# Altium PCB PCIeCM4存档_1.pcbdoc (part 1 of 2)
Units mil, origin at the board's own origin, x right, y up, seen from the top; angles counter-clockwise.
Board outline 9275 x 6345 mil, 4 copper layers (Top Layer, GND, 3V3, Bottom Layer); 98 components, 111 nets, 637 pads, 303 vias.
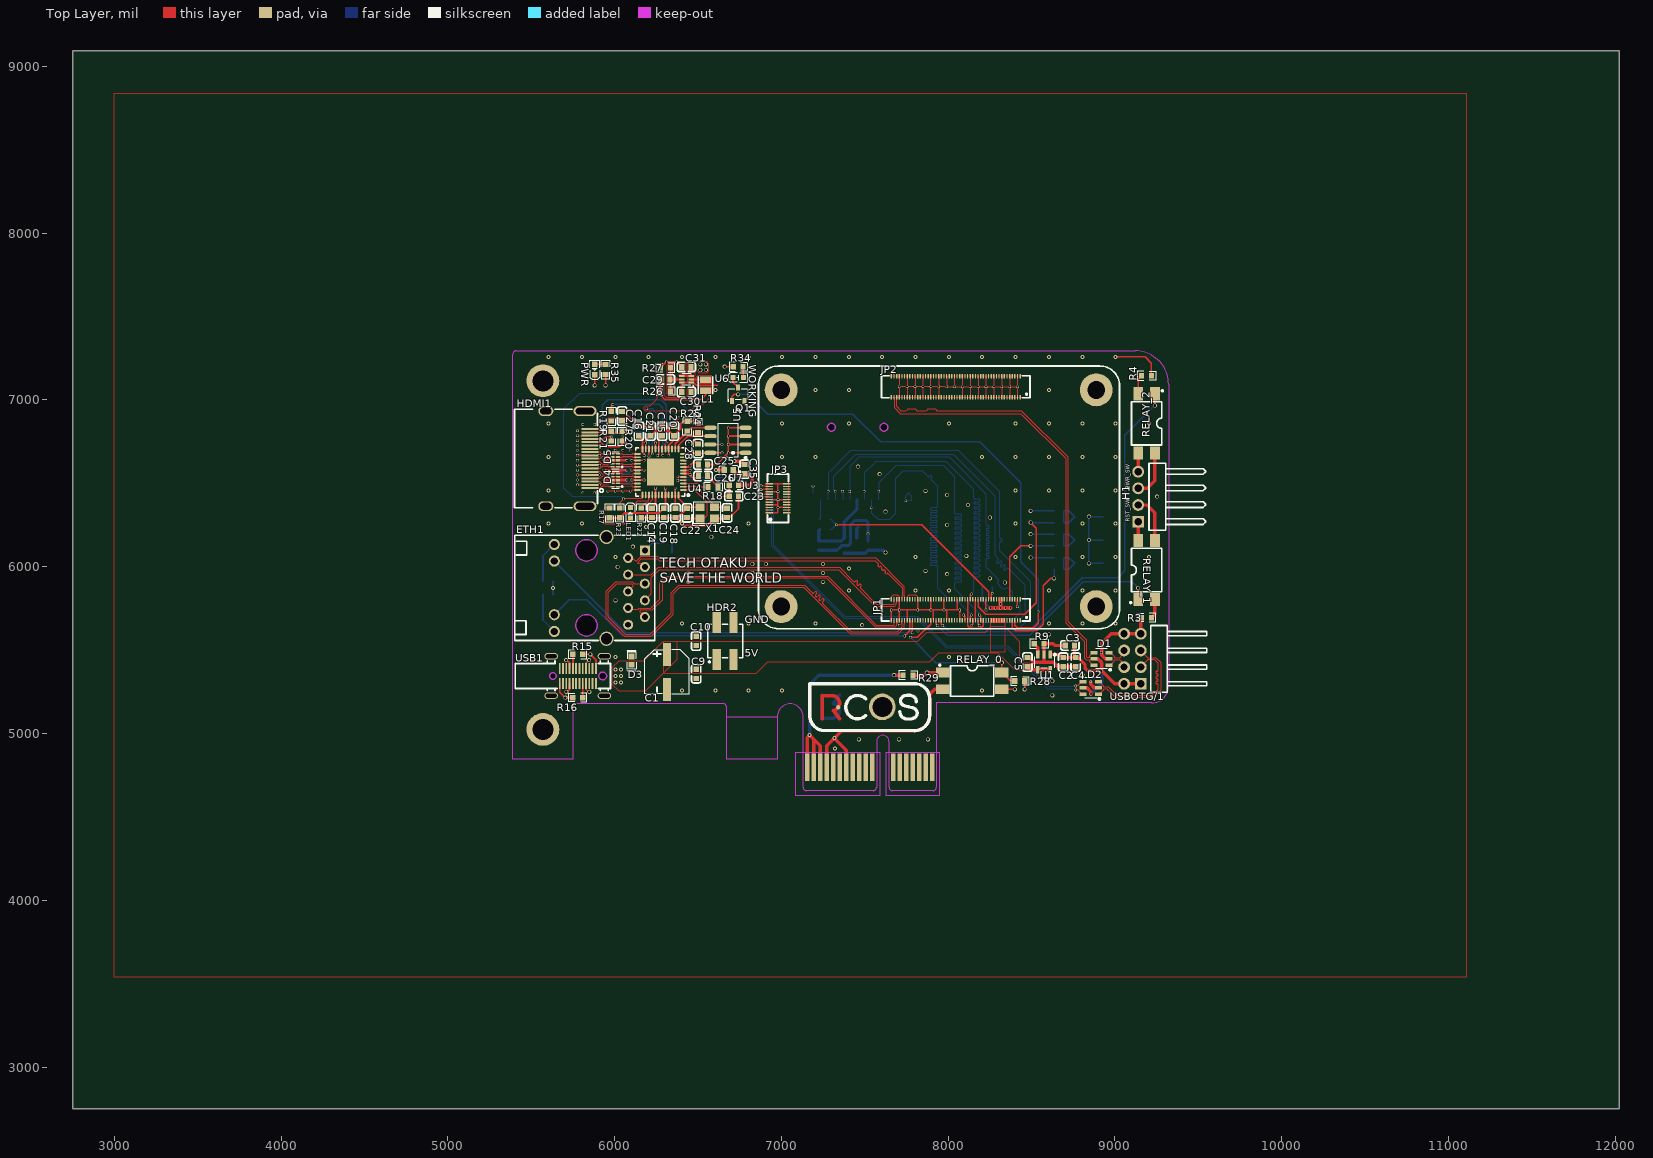
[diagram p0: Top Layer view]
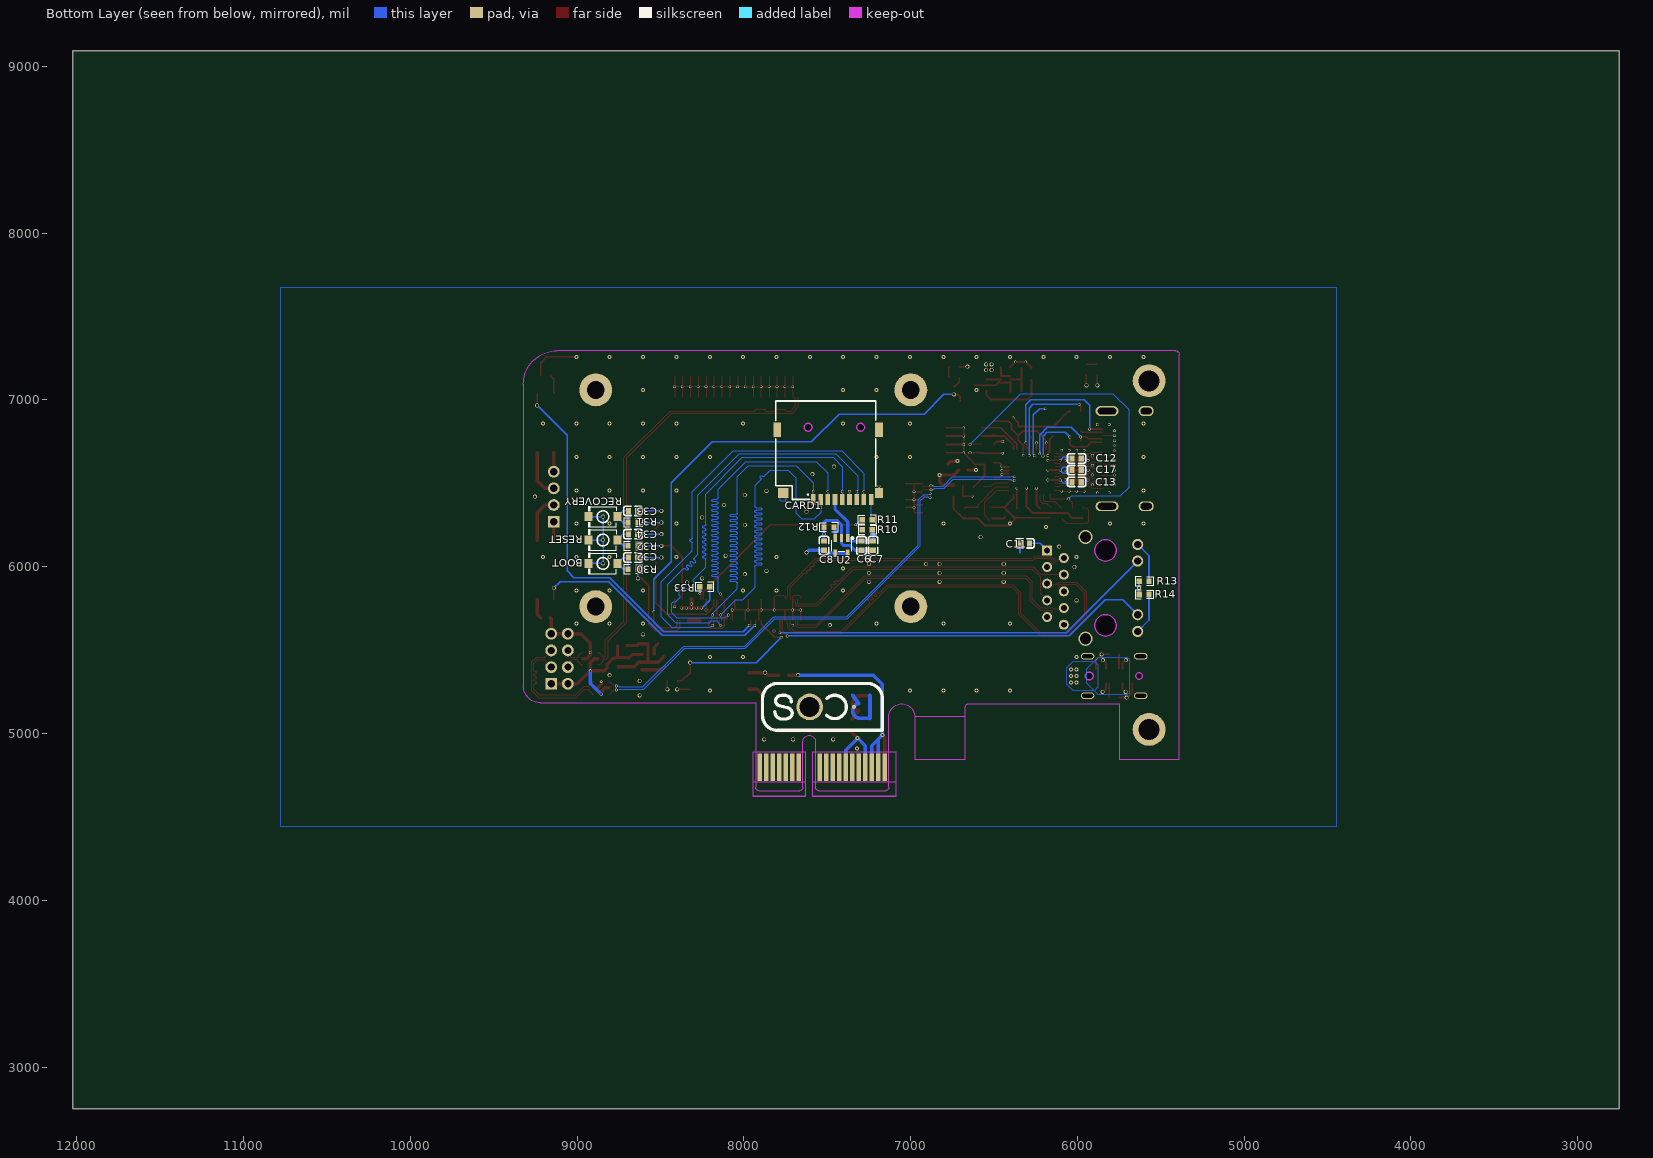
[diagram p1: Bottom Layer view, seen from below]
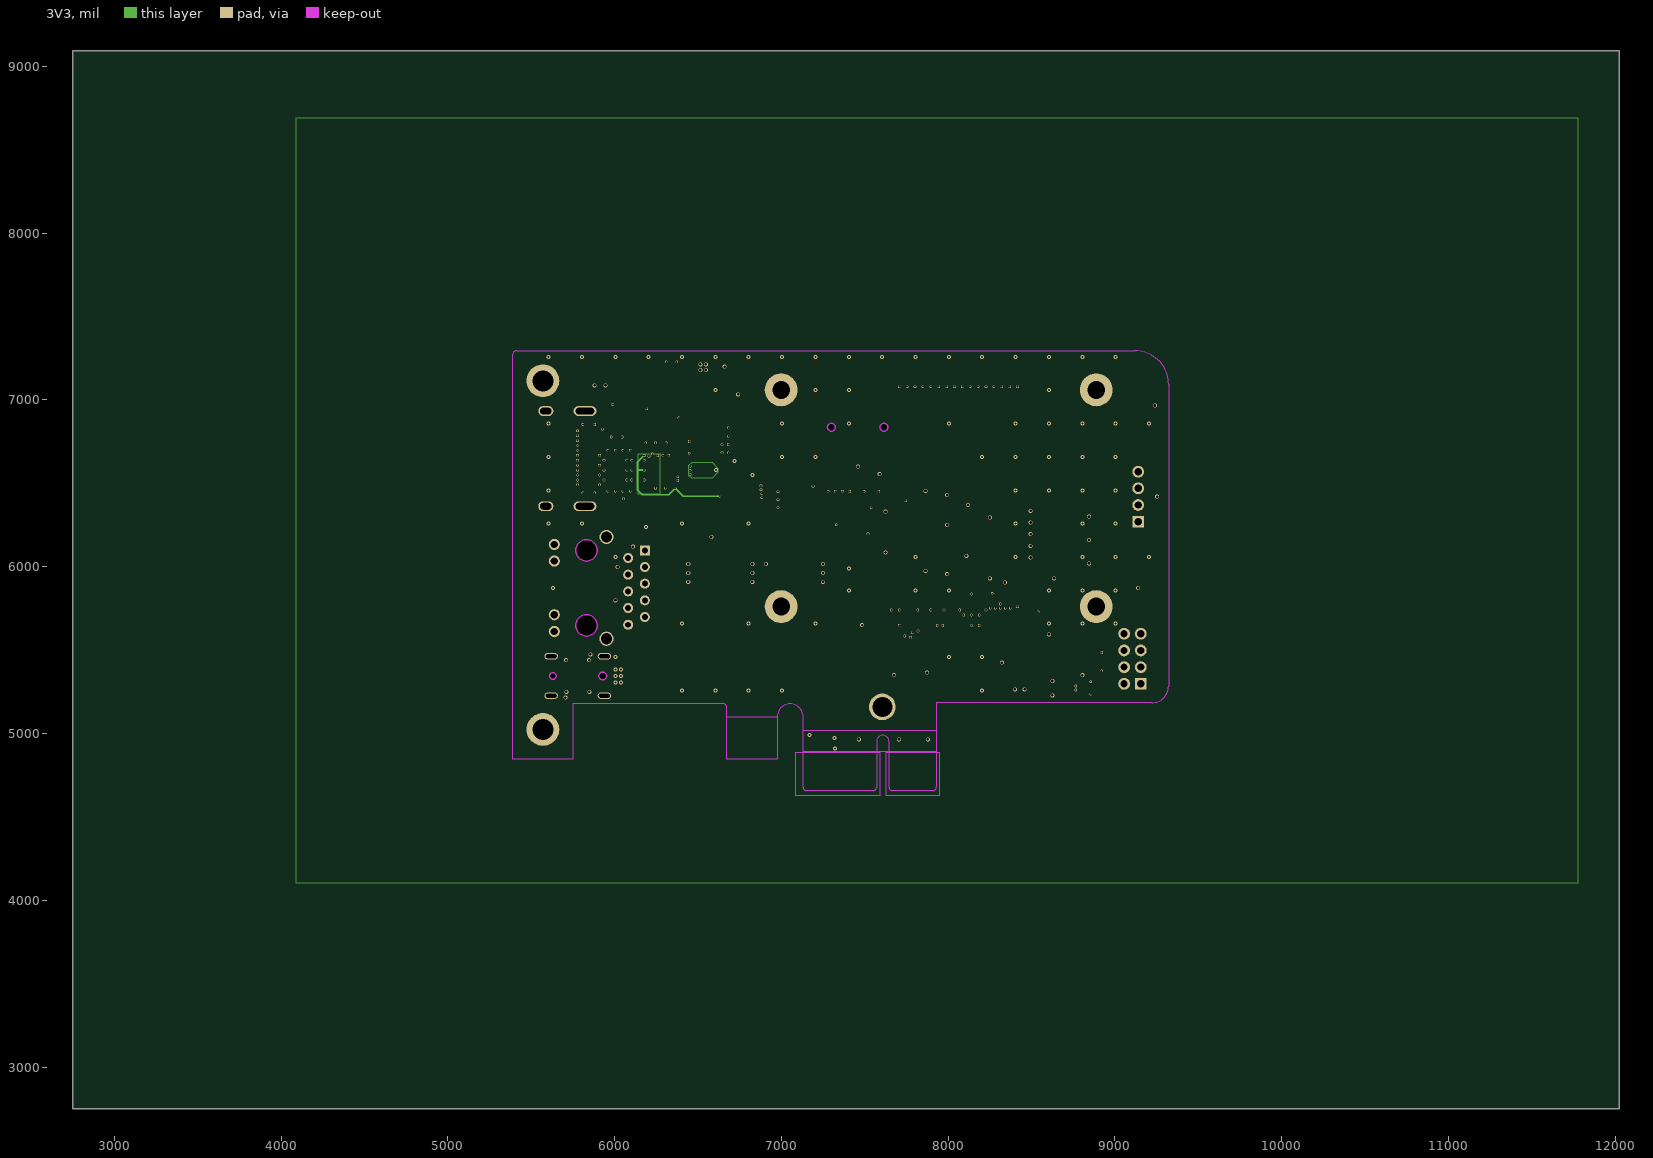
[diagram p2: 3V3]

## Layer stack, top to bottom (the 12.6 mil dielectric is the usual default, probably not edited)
Top Layer: signal copper (thickness not stored)
Dielectric: dielectric 12.6, FR-4, Dk 4.8
GND: signal copper (thickness not stored)
Dielectric: dielectric 12.6, FR-4, Dk 4.8
3V3: signal copper (thickness not stored)
Dielectric: dielectric 12.6, FR-4, Dk 4.8
Bottom Layer: signal copper (thickness not stored)

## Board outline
12025,2750 2750,2750 2750,9095 12025,9095

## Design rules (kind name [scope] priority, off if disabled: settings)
BoardOutlineClearance copperThickness1oz [All] p0: genericclearance=10 ignorepadtopadclearanceinfootprint=FALSE except(0: Arc-SplitContinuation Track-SplitContinuation SMDPad-SplitContinuation THPad-SplitContinuation Via-SplitContinuation Fill-SplitContinuation Poly-SplitContinuation Region-SplitContinuation Text-SplitContinuation; 6: Track-OutlineEdge SMDPad-OutlineEdge THPad-OutlineEdge Via-OutlineEdge Fill-OutlineEdge Region-OutlineEdge Poly-OutlineEdge Text-OutlineEdge Track-CutoutEdge SMDPad-CutoutEdge THPad-CutoutEdge Via-CutoutEdge Fill-CutoutEdge Region-CutoutEdge)
BoardOutlineClearance copperThickness2oz [All] p0: genericclearance=10 ignorepadtopadclearanceinfootprint=FALSE except(0: Arc-SplitContinuation Track-SplitContinuation SMDPad-SplitContinuation THPad-SplitContinuation Via-SplitContinuation Fill-SplitContinuation Poly-SplitContinuation Region-SplitContinuation Text-SplitContinuation; 6: Track-OutlineEdge SMDPad-OutlineEdge THPad-OutlineEdge Via-OutlineEdge Fill-OutlineEdge Region-OutlineEdge Poly-OutlineEdge Text-OutlineEdge Track-CutoutEdge SMDPad-CutoutEdge THPad-CutoutEdge Via-CutoutEdge Fill-CutoutEdge Region-CutoutEdge)
BoardOutlineClearance copperThicknessInner0.5oz [All] p0: genericclearance=10 ignorepadtopadclearanceinfootprint=FALSE except(0: Arc-SplitContinuation Track-SplitContinuation SMDPad-SplitContinuation THPad-SplitContinuation Via-SplitContinuation Fill-SplitContinuation Poly-SplitContinuation Region-SplitContinuation Text-SplitContinuation; 6: Track-OutlineEdge SMDPad-OutlineEdge THPad-OutlineEdge Via-OutlineEdge Fill-OutlineEdge Region-OutlineEdge Poly-OutlineEdge Text-OutlineEdge Track-CutoutEdge SMDPad-CutoutEdge THPad-CutoutEdge Via-CutoutEdge Fill-CutoutEdge Region-CutoutEdge)
Clearance copperThickness1oz [(InNet('GND') OR InNet('MDI0+') OR InNet('MDI0-') OR InNet('MDI1+') OR InNet('MDI2+') OR InNet('MDI2-') OR InNet('MDI1-') OR InNet('MDI3+') OR InNet('LED1') OR InNet('LED2') OR InNet('MDI3-') OR InNet('3V3') OR InNet('SDCMD') OR InNet('SDDET') OR InNet('SDD2') OR InNet('SDD1') OR InNet('SDD0') OR InNet('SDD3') OR InNet('SDCLK') OR InNet('VCCSD') OR InNet('RX') OR InNet('TX') OR InNet('1V2') OR InNet('A3V3') OR InNet('HXIN') OR InNet('HXOUT') OR InNet('HDMI_2P+') OR InNet('HDMI_2N-') OR InNet('HDMI_1P+') OR InNet('HDMI_1N-') OR InNet('HDMI_0P+') OR InNet('HDMI_0N-') OR InNet('HDMI_CP+') OR InNet('HDMI_CN-') OR InNet('HDMIHPD') OR InNet('HDMISCL') OR InNet('HDMISDA') OR InNet('LED') OR InNet('$6N3531') OR InNet('$6N3350') OR InNet('HDMIDET') OR InNet('WP') OR InNet('$6N3428') OR InNet('5V') OR InNet('VCCOTG') OR InNet('$4N2459') OR InNet('$6N6824') OR InNet('CM_SCL') OR InNet('CM_SDA') OR InNet('MS_SCL') OR InNet('MS_SDA') OR InNet('DM_OTG') OR InNet('DP_OTG') OR InNet('USB2_DM1') OR InNet('USB2_DP1') OR InNet('USB2_DM0') OR InNet('USB2_DP0') OR InNet('USB3_DM0') OR InNet('USB3_DP0') OR InNet('$4N5134') OR InNet('$4N5121') OR InNet('$4N5415') OR InNet('$4N5413') OR InNet('PWR_SW1') OR InNet('RST_SW1') OR InNet('PWR_SW2') OR InNet('RST_SW2') OR InNet('$1N34959') OR InNet('$1N34953') OR InNet('GPIO3_D4') OR InNet('GPIO3_D7') OR InNet('GPIO3_D0') OR InNet('GPIO3_D3') OR InNet('GPIO3_D1') OR InNet('GPIO3_D2') OR InNet('GPIO3_D5') OR InNet('GPIO4_C0') OR InNet('GPIO1_A1') OR InNet('GPIO4_A7') OR InNet('GPIO4_A6') OR InNet('GPIO4_A4') OR InNet('GPIO4_A1') OR InNet('GPIO4_A3') OR InNet('$6N28750') OR InNet('$6N28730') OR InNet('$4N7739') OR InNet('$4N7470') OR InNet('$4N7747') OR InNet('$4N7748') OR InNet('$4N7460') OR InNet('$4N11549') OR InNet('$4N11575') OR InNet('12V') OR InNet('$2N4077') OR InNet('SW_RECOVERY') OR InNet('BOOT-SW') OR InNet('WORK_LED') OR InNet('RESETN') OR InNet('USB3_SSTXN') OR InNet('USB3_SSTXP') OR InNet('USB3_SSRXP') OR InNet('USB3_SSRXN') OR InNet('$2N22853') OR InNet('$2N22954') OR InNet('$2N22981') OR InNet('$2N23478') OR InNet('$2N23475') OR InNet('$2N23477') OR InNet('$6N3355') OR InNet('PCGND') OR InNet('$1N39035'))] p1: gap=7 ignorepadtopadclearanceinfootprint=FALSE except(4: Track-Track; 6: Track-SMDPad SMDPad-SMDPad Track-THPad SMDPad-THPad THPad-THPad Track-Via SMDPad-Via THPad-Via Via-Via Track-Fill SMDPad-Fill THPad-Fill Via-Fill Fill-Fill Track-Region SMDPad-Region THPad-Region Via-Region Fill-Region Region-Region SMDPad-Poly THPad-Poly Via-Poly Fill-Poly Region-Poly Poly-Poly Track-Text SMDPad-Text THPad-Text Via-Text Fill-Text Region-Text Text-Text Track-Sheet SMDPad-Sheet THPad-Sheet Via-Sheet Fill-Sheet Region-Sheet Poly-Sheet Text-Sheet Track-Hole SMDPad-Hole THPad-Hole Via-Hole Fill-Hole Region-Hole Poly-Hole Text-Hole Sheet-Hole; 11.8: Track-Poly Poly-Text)
Clearance copperThickness2oz [All] p1: gap=7 ignorepadtopadclearanceinfootprint=FALSE except(6: Track-SMDPad SMDPad-SMDPad Track-THPad SMDPad-THPad THPad-THPad Track-Via SMDPad-Via THPad-Via Via-Via Track-Fill SMDPad-Fill THPad-Fill Via-Fill Fill-Fill Track-Region SMDPad-Region THPad-Region Via-Region Fill-Region Region-Region SMDPad-Poly THPad-Poly Via-Poly Fill-Poly Region-Poly Poly-Poly Track-Text SMDPad-Text THPad-Text Via-Text Fill-Text Region-Text Text-Text Track-Sheet SMDPad-Sheet THPad-Sheet Via-Sheet Fill-Sheet Region-Sheet Poly-Sheet Text-Sheet Track-Hole SMDPad-Hole THPad-Hole Via-Hole Fill-Hole Region-Hole Poly-Hole Text-Hole Sheet-Hole; 8: Track-Track; 11.8: Track-Poly Poly-Text)
Clearance copperThicknessInner0.5oz [All] p1: gap=7 ignorepadtopadclearanceinfootprint=FALSE except(3.5: Track-Track; 6: Track-SMDPad SMDPad-SMDPad Track-THPad SMDPad-THPad THPad-THPad Track-Via SMDPad-Via THPad-Via Via-Via Track-Fill SMDPad-Fill THPad-Fill Via-Fill Fill-Fill Track-Region SMDPad-Region THPad-Region Via-Region Fill-Region Region-Region SMDPad-Poly THPad-Poly Via-Poly Fill-Poly Region-Poly Poly-Poly Track-Text SMDPad-Text THPad-Text Via-Text Fill-Text Region-Text Text-Text Track-Sheet SMDPad-Sheet THPad-Sheet Via-Sheet Fill-Sheet Region-Sheet Poly-Sheet Text-Sheet Track-Hole SMDPad-Hole THPad-Hole Via-Hole Fill-Hole Region-Hole Poly-Hole Text-Hole Sheet-Hole; 11.8: Track-Poly Poly-Text)
DiffPairsRouting differentialPair [All] p1: maxuncoupledlength=10 minlimit=7.9921 maxlimit=7.9921 mostfreqgap=7.9921 toplayer_minwidth=4.0158 toplayer_prefwidth=5 toplayer_maxwidth=100 bottomlayer_minwidth=4.0158 bottomlayer_prefwidth=5 bottomlayer_maxwidth=100 midlayer1_minwidth=4.0158 midlayer1_prefwidth=5 midlayer1_maxwidth=100 midlayer2_minwidth=4.0158 midlayer2_prefwidth=5 midlayer2_maxwidth=100
PasteMaskExpansion pasteMaskExpansion [All] p1: expansion=0
PlaneConnect innerPlane [All] p1: planeconnectstyle=Relief reliefexpansion=20 reliefentries=4 reliefconductorwidth=10 reliefairgap=10
PolygonConnect 1 [All] p1: connectstyle=Direct reliefentries=4 reliefconductorwidth=10 polygonreliefangle="90 Angle" airgapwidth=10
PolygonConnect copperRegion [All] p1: connectstyle=Relief reliefentries=4 reliefconductorwidth=10 polygonreliefangle="90 Angle" airgapwidth=10
RoutingVias viaSize [All] p1: viastyle="Through Hole" holewidth=11.811 minholewidth=11.811 maxholewidth=247.9922 width=24.0158 minwidth=15.748 maxwidth=393.7008
SolderMaskExpansion solderMaskExpansion [All] p1: useseparateexpansions=TRUE expansion=2.0079 expansionbottom=2.0079
Width copperThickness1oz [All] p1: maxlimit=100 minlimit=4 preferedwidth=10
Width copperThickness2oz [All] p1: maxlimit=100 minlimit=8 preferedwidth=10
Width copperThickness0.5oz [All] p1: maxlimit=100 minlimit=4 preferedwidth=10

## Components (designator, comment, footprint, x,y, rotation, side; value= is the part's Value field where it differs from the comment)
BOOT "TS-1088-AR02016" SW-SMD_L3.9-W3.0-P4.45 8844.42,6020 r0 bottom
C1 "HV1J106M0605PZ" CAP-SMD_BD6.3-L6.6-W6.6-LS7.2-FD 6314.42,5370 r270 top
C2 "CC0603KRX7R9BB104" C0603 8690,5428.08 r90 top
C3 "CL10A105KB8NNNC" C0603 8730,5528.08 r0 top
C4 "CC0603KRX7R9BB104" C0603 8765,5428.08 r90 top
C5 "CC0603KRX7R9BB104" C0603 8475,5428.08 r270 top
C6 "CC0603KRX7R9BB104" C0603 7294.62,6126.77 r90 bottom
C7 "CL10A106MO8NQNC" C0603 7224.62,6126.77 r270 bottom
C8 "CC0603KRX7R9BB104" C0603 7519.62,6126.77 r270 bottom
C9 "CL10A105KB8NNNC" C0603 6489.42,5358 r270 top
C10 "CC0603KRX7R9BB104" C0603 6489.42,5555 r90 top
C11 "CC0603KRX7R9BB104" C0603 6314.42,6140 r180 bottom
C12 "CC0603KRX7R9BB104" C0603 6005,6649.18 r0 bottom
C13 "CC0603KRX7R9BB104" C0603 6005,6509.18 r0 bottom
C14 "CC0603KRX7R9BB104" C0603 6225,6323.08 r90 top
C15 "CC0603KRX7R9BB104" C0603 6285,6813.08 r270 top
C16 "CC0603KRX7R9BB104" C0603 6145,6813.08 r270 top
C17 "CC0603KRX7R9BB104" C0603 6005,6579.18 r0 bottom
C18 "CC0603KRX7R9BB104" C0603 6365,6323.08 r90 top
C19 "CC0603KRX7R9BB104" C0603 6295,6323.08 r90 top
C20 "CC0603KRX7R9BB104" C0603 6355,6813.08 r270 top
C21 "CC0603KRX7R9BB104" C0603 6215,6813.08 r270 top
C22 "CL10C120JB8NNNC" C0603 6435,6323.08 r90 top
C23 "CL10A226MQ8NRNC" C0603 6715.32,6422.77 r180 top
C24 "CL10C120JB8NNNC" C0603 6675,6323.08 r270 top
C25 "CC0603KRX7R9BB104" C0603 6530,6613.08 r180 top
C26 "CC0603KRX7R9BB104" C0603 6530,6543.08 r180 top
C27 "CC0603KRX7R9BB104" C0603 6045,6903.08 r270 top
C28 "CC0603KRX7R9BB104" C0603 6500,6708.08 r270 top
C29 "CL10C220JB8NNNC" C0603 6305,7123.08 r180 top
C30 "CL10A226MQ8NRNC" C0603 6430,7048.08 r0 top
C31 "CL10A475KO8NNNC" C0603 6430,7198.08 r0 top
C32 "CC0603KRX7R9BB104" C0603 8664.42,6055 r180 bottom
C33 "CC0603KRX7R9BB104" C0603 8664.42,6335 r180 bottom
C34 "CC0603KRX7R9BB104" C0603 8664.42,6195 r180 bottom
C35 "CL10A105KB8NNNC" C0603 6779.42,6585 r270 top
CARD1 "TF PUSH" TF-SMD_TF-PUSH 7494.62,6611.77 r0 bottom locked
D1 "USBLC6-2SC6_C7519" SOT-23-6_L2.9-W1.6-P0.95-LS2.8-BL 8920,5448.08 r90 top
D2 "USBLC6-2SC6_C7519" SOT-23-6_L2.9-W1.6-P0.95-LS2.8-BL 8855,5273.08 r90 top
D3 "EZAEG3A50AV" D0603-BI 6102.42,5437 r90 top
D4 "TPD4E05U06DQAR_C138714" USON-10_L2.5-W1.0-P0.50-BL 6005,6519.97 r90 top
D5 "TPD4E05U06DQAR_C138714" USON-10_L2.5-W1.0-P0.50-BL 6005,6638.08 r90 top
ETH1 "HR911130A" RJ45-TH_HR911130A 5910,5873.08 r90 top
H1 "PZ254R-11-04P" HDR-TH_4P-P2.54-H-M-W10.4 9139.42,6420 r90 top
HDMI1 "HDMI-001S" HDMI-SMD_HDMI-001S 5720,6648.08 r270 top
HDR2 "PZ254-2-02-S" HDR-SMD_4P-P2.54-V-M-R2-C2-LS7.5 6663.42,5554.5 r0 top
JP1 "DF40C-100DS-0.4V(51)" CONN-SMD_DF40C-100DS-0.4V-51 8045.54,5740.96 r0 top
JP2 "DF40C-100DS-0.4V(51)" CONN-SMD_DF40C-100DS-0.4V-51 8045.54,7079.57 r0 top
JP3 "DF40C-24DS-0.4V(51)" CONN-SMD_DF40C-24DS-0.4V51 6979.52,6410.61 r270 top
L1 "FTC201610S1R0MBCA" IND-SMD_L2.0-W1.6-B 6545,7088.08 r90 top
LED1 "NCD0603R1_C84263" LED0603-RD_RED 6095,6323.08 r270 top
PWR "NCD0603R1_C84263" LED0603-RD_RED 5880.74,7182.59 r90 top
Q1 "2SK3018" SOT-23-3_L2.9-W1.4-P1.90-LS2.6-BR 6740.74,7034.13 r270 top
R3 "0603WAF4700T5E" R0603 9189.42,5695 r0 top
R4 "0603WAF4700T5E" R0603 9189.42,7145 r180 top
R9 "0603WAF6801T5E" R0603 8545,5538.08 r180 top
R10 "0603WAF1001T5E" R0603 7259.62,6221.77 r0 bottom
R11 "0603WAF2000T5E" R0603 7259.62,6281.77 r180 bottom
R12 "0603WAF6801T5E" R0603 7489.62,6236.77 r180 bottom
R13 "0603WAF4700T5E" R0603 5600,5913.08 r0 bottom
R14 "0603WAF4700T5E" R0603 5600,5833.08 r0 bottom
R15 "RT0603BRD075K1L" R0603 5779.42,5475 r0 top
R16 "RT0603BRD075K1L" R0603 5779.42,5215 r0 top
R17 "0603WAF1001T5E" R0603 5970,6323.08 r270 top
R18 "0603WAF4701T5E" R0603 6590,6478.08 r180 top
R19 "0603WAF1001T5E" R0603 5980,6903.08 r270 top
R20 "0603WAF4701T5E" R0603 6045,6783.08 r270 top
R21 "0603WAF4701T5E" R0603 5980,6783.08 r270 top
R22 "0603WAF0000T5E" R0603 6160,6323.08 r270 top
R23 "0603WAF4701T5E" R0603 6030,6323.08 r270 top
R24 "0603WAF4701T5E" R0603 6500,6833.08 r90 top
R25 "0603WAF4701T5E" R0603 6435,6843.08 r90 top
R26 "0603WAF2003T5E" R0603 6305,7053.08 r180 top
R27 "0603WAF1003T5E" R0603 6305,7193.08 r0 top
R28 "0603WAF1002T5E" R0603 8429.42,5315 r180 top
R29 "0603WAF2201T5E" R0603 7759.42,5350 r180 top
R30 "0603WAF0000T5E" R0603 8664.42,5985 r0 bottom
R31 "0603WAF220JT5E" R0603 8664.42,6265 r0 bottom
R32 "0603WAF220JT5E" R0603 8664.42,6125 r0 bottom
R33 "0603WAF0000T5E" R0603 8234.42,5880 r180 bottom
R34 "0603WAF4700T5E" R0603 6740.74,7199.13 r180 top
R35 "0603WAF2201T5E" R0603 5945.74,7182.59 r270 top
RECOVERY "TS-1088-AR02016" SW-SMD_L3.9-W3.0-P4.45 8844.42,6300 r0 bottom
RELAY_0 "G3VM-61D1(TR)" SMD-4_L4.6-W6.4-P2.54-LS10.0-BL 8144.42,5315 r270 top
RELAY_1 "G3VM-61D1(TR)" SMD-4_L4.6-W6.4-P2.54-LS10.0-BL 9189.42,5980 r0 top
RELAY_2 "G3VM-61D1(TR)" SMD-4_L4.6-W6.4-P2.54-LS10.0-BL 9189.42,6860 r180 top
RESET "TS-1088-AR02016" SW-SMD_L3.9-W3.0-P4.45 8844.42,6160 r0 bottom
U1 "SY6280AAC_C55136" SOT-23-5_L3.0-W1.7-P0.95-LS2.8-BL 8575,5428.08 r180 top
U2 "SY6280AAC_C55136" SOT-23-5_L3.0-W1.7-P0.95-LS2.8-BL 7414.62,6126.77 r0 bottom
U3 "BLM18PG121SN1D" L0603 6715.32,6487.77 r0 top
U4 "MS2109" QFN-48_L7.0-W7.0-P0.50-TL-EP4.1 6275,6568.08 r180 top
U5 "AT24C16M/TR" SOP-8_L4.9-W3.9-P1.27-LS6.0-BL 6680,6758.08 r90 top
U6 "TPS62A01DRLR" SOT-5X3-6_L1.6-W1.2-P0.50-LS1.6-BR 6430,7123.08 r0 top
U7 "BLM18PG121SN1D" L0603 6684.42,6580 r0 top
USB1 "U264-2430N-4BSK00" USB-C-SMD_HC-TYPE-C-24P-FLS-CH5.06-5A-23 5779.42,5345 r270 top
USBOTG/1 "PZ254R-12-8P" HDR-TH_8P-P2.54-H-M-R2-C4-S2.54 9105,5448.08 r90 top
WORKING "NCD0603G1" LED0603-RD_1 6740.74,7134.13 r0 top
X1 "TXM24M0004322FBCDO00T" CRYSTAL-SMD_4P-L3.2-W2.5-BL 6555,6323.08 r0 top

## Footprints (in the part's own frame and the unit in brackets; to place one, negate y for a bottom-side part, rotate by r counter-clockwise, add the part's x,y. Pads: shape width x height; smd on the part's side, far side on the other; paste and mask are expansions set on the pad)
C0603 [mm]
  rect 0.8x0.9 smd: 1(-0.7,0) 2(0.7,0)
  silkscreen extent -1.41,-0.71 1.39,0.72
CAP-SMD_BD6.3-L6.6-W6.6-LS7.2-FD [mm]
  rect 3.5x1.2 smd: 1(-2.67,0) 2(2.67,0)
  silkscreen extent -3.38,-3.38 3.38,3.38
CONN-SMD_DF40C-24DS-0.4V51 [mm]
  rect 0.2x1.14 smd: 1(2.2,-1.32) 2(2.2,1.32) 3(1.8,-1.32) 4(1.8,1.32) 5(1.4,-1.32) 6(1.4,1.32) 7(1,-1.32) 8(1,1.32) 9(0.6,-1.32) 10(0.6,1.32) 11(0.2,-1.32) 12(0.2,1.32) 13(-0.2,-1.32) 14(-0.2,1.32) 15(-0.6,-1.32) 16(-0.6,1.32) 17(-1,-1.32) 18(-1,1.32) 19(-1.4,-1.32) 20(-1.4,1.32) 21(-1.8,-1.32) 22(-1.8,1.32) 23(-2.2,-1.32) 24(-2.2,1.32)
  silkscreen extent -3.68,-1.6 3.7,1.6
CONN-SMD_DF40C-100DS-0.4V-51 [mm]
  rect 0.2x0.7 smd: 1(9.8,-1.6) 2(9.4,-1.6) 3(9,-1.6) 4(8.6,-1.6) 5(8.2,-1.6) 6(7.8,-1.6) 7(7.4,-1.6) 8(7,-1.6) 9(6.6,-1.6) 10(6.2,-1.6) 11(5.8,-1.6) 12(5.4,-1.6) 13(5,-1.6) 14(4.6,-1.6) 15(4.2,-1.6) 16(3.8,-1.6) 17(3.4,-1.6) 18(3,-1.6) 19(2.6,-1.6) 20(2.2,-1.6) 21(1.8,-1.6) 22(1.4,-1.6) 23(1,-1.6) 24(0.6,-1.6) 25(0.2,-1.6) 26(-0.2,-1.6) 27(-0.6,-1.6) 28(-1,-1.6) 29(-1.4,-1.6) 30(-1.8,-1.6) 31(-2.2,-1.6) 32(-2.6,-1.6) 33(-3,-1.6) 34(-3.4,-1.6) 35(-3.8,-1.6) 36(-4.2,-1.6) 37(-4.6,-1.6) 38(-5,-1.6) 39(-5.4,-1.6) 40(-5.8,-1.6) 41(-6.2,-1.6) 42(-6.6,-1.6) 43(-7,-1.6) 44(-7.4,-1.6) 45(-7.8,-1.6) 46(-8.2,-1.6) 47(-8.6,-1.6) 48(-9,-1.6) 49(-9.4,-1.6) 50(-9.8,-1.6) 51(-9.8,1.6) 52(-9.4,1.6) 53(-9,1.6) 54(-8.6,1.6) 55(-8.2,1.6) 56(-7.8,1.6) 57(-7.4,1.6) 58(-7,1.6) 59(-6.6,1.6) 60(-6.2,1.6) 61(-5.8,1.6) 62(-5.4,1.6) 63(-5,1.6) 64(-4.6,1.6) 65(-4.2,1.6) 66(-3.8,1.6) 67(-3.4,1.6) 68(-3,1.6) 69(-2.6,1.6) 70(-2.2,1.6) 71(-1.8,1.6) 72(-1.4,1.6) 73(-1,1.6) 74(-0.6,1.6) 75(-0.2,1.6) 76(0.2,1.6) 77(0.6,1.6) 78(1,1.6) 79(1.4,1.6) 80(1.8,1.6) 81(2.2,1.6) 82(2.6,1.6) 83(3,1.6) 84(3.4,1.6) 85(3.8,1.6) 86(4.2,1.6) 87(4.6,1.6) 88(5,1.6) 89(5.4,1.6) 90(5.8,1.6) 91(6.2,1.6) 92(6.6,1.6) 93(7,1.6) 94(7.4,1.6) 95(7.8,1.6) 96(8.2,1.6) 97(8.6,1.6) 98(9,1.6) 99(9.4,1.6) 100(9.8,1.6)
  silkscreen extent -11.3,-1.69 11.3,1.69
CRYSTAL-SMD_4P-L3.2-W2.5-BL [mm]
  rect 1.4x1.2 smd: 1(-1.1,-0.85) 2(1.1,-0.85) 3(1.1,0.85) 4(-1.1,0.85)
  silkscreen extent -2.26,-1.91 2.03,1.68
D0603-BI [mil]
  rect 34.38x35.72 smd: 1(-24.47,0) 2(24.47,0)
  silkscreen extent -60,-27 60,27
HDMI-SMD_HDMI-001S [mm]
  rect 0.3x2.6 smd: 1(4.5,3.36) 2(4,3.36) 3(3.5,3.36) 4(3,3.36) 5(2.5,3.36) 6(2,3.36) 7(1.5,3.36) 8(1,3.36) 9(0.5,3.36) 10(0,3.36) 11(-0.5,3.36) 12(-1,3.36) 13(-1.5,3.36) 14(-2,3.36) 15(-2.5,3.36) 16(-3,3.36) 17(-3.5,3.36) 18(-4,3.36) 19(-4.5,3.36)
  oval 1.5x3.5 hole 1 slot 2.8 at 90 deg: 20(-7.25,2.6) 21(7.25,2.6)
  oval 1.5x2.3 hole 1 slot 1.7 at 90 deg: 22(-7.25,-3.36) 23(7.25,-3.36)
  silkscreen extent -7.5,-8.12 7.5,5.39
HDR-SMD_4P-P2.54-V-M-R2-C2-LS7.5 [mm]
  rect 1.27x3.17 smd: 1(-1.27,-2.8) 2(-1.27,2.8) 3(1.27,-2.8) 4(1.27,2.8)
  silkscreen extent -2.67,-3.3 2.67,2.54
HDR-TH_4P-P2.54-H-M-W10.4 [mm]
  rect 1.8x1.8 hole 1.1: 1(-3.81,0)
  round 1.8 hole 1.1: 2(-1.27,0) 3(1.27,0) 4(3.81,0)
  silkscreen extent -5.09,-10.27 5.07,-1.65
HDR-TH_8P-P2.54-H-M-R2-C4-S2.54 [mm]
  rect 1.778x1.8 hole 1.1: 1(-3.81,-1.27)
  round 1.8 hole 1.1: 2(-3.81,1.27) 3(-1.27,-1.27) 4(-1.27,1.27) 5(1.27,-1.27) 6(1.27,1.27) 7(3.81,-1.27) 8(3.81,1.27)
  silkscreen extent -5.07,-11.3 5.07,-2.8
IND-SMD_L2.0-W1.6-B [mm]
  rect 1x1.7 smd: 1(-0.85,0) 2(0.85,0)
  silkscreen extent -1.27,-1.12 1.27,1.12
L0603 [mm]
  rect 0.8x0.864 smd: 1(-0.7,0) 2(0.7,0)
  silkscreen extent -1.42,-0.65 1.42,0.65
LED0603-RD_1 [mm]
  rect 0.8x0.8 smd: 1(-0.799,-0.004) 2(0.799,0.004)
  silkscreen extent -1.49,-0.75 1.39,0.76
LED0603-RD_RED [mm]
  rect 0.8x0.8 smd: 1(-0.8,-0.003) 2(0.8,0.003)
  silkscreen extent -1.49,-0.75 1.39,0.76
QFN-48_L7.0-W7.0-P0.50-TL-EP4.1 [mm]
  oval 1x0.28 smd: 1(-3.5,2.75) 2(-3.5,2.25) 3(-3.5,1.75) 4(-3.5,1.25) 5(-3.5,0.75) 6(-3.5,0.25) 7(-3.5,-0.25) 8(-3.5,-0.75) 9(-3.5,-1.25) 10(-3.5,-1.75) 11(-3.5,-2.25) 12(-3.5,-2.75) 25(3.5,-2.75) 26(3.5,-2.25) 27(3.5,-1.75) 28(3.5,-1.25) 29(3.5,-0.75) 30(3.5,-0.25) 31(3.5,0.25) 32(3.5,0.75) 33(3.5,1.25) 34(3.5,1.75) 35(3.5,2.25) 36(3.5,2.75)
  oval 0.28x1 smd: 13(-2.75,-3.5) 14(-2.25,-3.5) 15(-1.75,-3.5) 16(-1.25,-3.5) 17(-0.75,-3.5) 18(-0.25,-3.5) 19(0.25,-3.5) 20(0.75,-3.5) 21(1.25,-3.5) 22(1.75,-3.5) 23(2.25,-3.5) 24(2.75,-3.5) 37(2.75,3.5) 38(2.25,3.5) 39(1.75,3.5) 40(1.25,3.5) 41(0.75,3.5) 42(0.25,3.5) 43(-0.25,3.5) 44(-0.75,3.5) 45(-1.25,3.5) 46(-1.75,3.5) 47(-2.25,3.5) 48(-2.75,3.5)
  rect 4.1x4.1 smd: 49(0,0)
  silkscreen extent -4.4,-3.72 3.73,3.73
R0603 [mil]
  rect 31.75x34.02 smd: 1(-29.66,0) 2(29.66,0)
  silkscreen extent -55,-26 55,26
RJ45-TH_HR911130A [mil]
  round 66.93 hole 43.31: 11(260.83,271.46) 12(160.83,271.46) 13(-160.83,271.46) 14(-260.83,271.46)
  rect 60x60 hole 35.83: P1(225.2,-271.45)
  round 60 hole 35.83: P2(179.1,-171.45) P3(125.2,-271.45) P4(79.1,-171.45) P5(25.2,-271.45) P6(-20.9,-171.45) P7(-74.8,-271.45) P8(-120.9,-171.45) P9(-174.8,-271.45) P10(-220.9,-171.45)
  round 85 hole 66.93: SHIELD0(-304.92,-41.56) SHIELD1(304.92,-41.56)
  Board Outline Layer circle w0.2: c-225,78.55 r63.98
  Board Outline Layer circle w0.2: c225,78.55 r63.98
  Board Outline Layer region: -225,14.57 -252.76,20.9 -275.02,38.66 -287.37,64.31 -287.37,92.78 -275.02,118.43 -252.76,136.19 -225,142.52 -225,142.52 -197.24,136.19 -174.98,118.43 -162.63,92.78 -162.63,64.31 -174.98,38.66 -197.24,20.9 -225,14.57
  Board Outline Layer region: 225,14.57 197.24,20.9 174.98,38.66 162.63,64.31 162.63,92.78 174.98,118.43 197.24,136.19 225,142.52 225,142.52 252.76,136.19 275.02,118.43 287.37,92.78 287.37,64.31 275.02,38.66 252.76,20.9 225,14.57
  Multi-Layer board cut-out: -225,14.57 -252.76,20.9 -275.02,38.66 -287.37,64.31 -287.37,92.78 -275.02,118.43 -252.76,136.19 -225,142.52 -225,142.52 -197.24,136.19 -174.98,118.43 -162.63,92.78 -162.63,64.31 -174.98,38.66 -197.24,20.9 -225,14.57
  Multi-Layer board cut-out: 225,14.57 197.24,20.9 174.98,38.66 162.63,64.31 162.63,92.78 174.98,118.43 197.24,136.19 225,142.52 225,142.52 252.76,136.19 275.02,118.43 287.37,92.78 287.37,64.31 275.02,38.66 252.76,20.9 225,14.57
  silkscreen extent -316,-331 316,508
SMD-4_L4.6-W6.4-P2.54-LS10.0-BL [mm]
  rect 1.5x2 smd: 1(-1.27,-4.5) 2(1.27,-4.5) 3(1.27,4.5) 4(-1.27,4.5)
  silkscreen extent -2.54,-5.08 2.3,3.3
SOP-8_L4.9-W3.9-P1.27-LS6.0-BL [mm]
  oval 0.63x1.865 smd: 1(-1.905,-2.682) 2(-0.635,-2.682) 3(0.635,-2.682) 4(1.905,-2.682) 5(1.905,2.682) 6(0.635,2.682) 7(-0.635,2.682) 8(-1.905,2.682)
  silkscreen extent -2.82,-2.83 2.58,1.52
SOT-5X3-6_L1.6-W1.2-P0.50-LS1.6-BR [mm]
  rect 0.85x0.3 smd: 1(0.725,-0.5) 2(0.725,0) 3(0.725,0.5) 4(-0.725,0.5) 5(-0.725,0) 6(-0.725,-0.5)
  silkscreen extent -0.65,-1 1.1,0.9
SOT-23-3_L2.9-W1.4-P1.90-LS2.6-BR [mm]
  rect 0.91x0.6 smd: 1(1.055,-0.955) 2(1.055,0.955) 3(-1.055,0)
  silkscreen extent -0.78,-1.6 1.09,1.53
SOT-23-5_L3.0-W1.7-P0.95-LS2.8-BL [mm]
  rect 0.49x1.157 smd: 1(-0.95,-1.154) 2(0,-1.154) 3(0.95,-1.154)
  rect 0.49x1.175 smd: 4(0.95,1.154) 5(-0.95,1.154)
  silkscreen extent -1.8,-1.29 1.53,0.85
SOT-23-6_L2.9-W1.6-P0.95-LS2.8-BL [mil]
  rect 20.95x42.2 smd: 1(-37.4,-45.24) 2(0,-45.24) 3(37.4,-45.24) 4(37.4,45.24) 5(0,45.24) 6(-37.4,45.24)
  silkscreen extent -72,-57 61,35
SW-SMD_L3.9-W3.0-P4.45 [mm]
  rect 1.23x1.36 smd: 1(-2.185,0) 2(2.185,0)
  silkscreen extent -2.03,-1.62 2.25,1.62
TF-SMD_TF-PUSH [mm]
  rect 0.7x1.6 smd: 1(2.25,5.3) 2(1.15,5.3) 3(0.05,5.3) 4(-1.05,5.3) 5(-2.15,5.3) 6(-3.25,5.3) 7(-4.35,5.3) 8(-5.45,5.3) CD(-6.55,5.3)
  rect 1.2x1.5 smd: 10(-7.75,4.3)
  rect 1.2x2.2 smd: 11(-7.75,-5.3) 12(7.75,-5.3)
  rect 1.6x1.5 smd: 13(6.85,4.3)
  Board Outline Layer circle w0.005: c-4.95,-5.7 r0.6
  Board Outline Layer circle w0.005: c3.05,-5.7 r0.6
  Board Outline Layer region: -4.35,-5.7 -4.409,-5.44 -4.576,-5.231 -4.816,-5.115 -5.083,-5.115 -5.324,-5.231 -5.491,-5.44 -5.55,-5.7 -5.55,-5.7 -5.491,-5.96 -5.324,-6.169 -5.083,-6.285 -4.816,-6.285 -4.576,-6.169 -4.409,-5.96 -4.35,-5.7
  Board Outline Layer region: 3.65,-5.7 3.591,-5.44 3.424,-5.231 3.184,-5.115 2.917,-5.115 2.676,-5.231 2.509,-5.44 2.45,-5.7 2.45,-5.7 2.509,-5.96 2.676,-6.169 2.917,-6.285 3.184,-6.285 3.424,-6.169 3.591,-5.96 3.65,-5.7
  Multi-Layer board cut-out: -4.35,-5.7 -4.409,-5.44 -4.576,-5.231 -4.816,-5.115 -5.083,-5.115 -5.324,-5.231 -5.491,-5.44 -5.55,-5.7 -5.55,-5.7 -5.491,-5.96 -5.324,-6.169 -5.083,-6.285 -4.816,-6.285 -4.576,-6.169 -4.409,-5.96 -4.35,-5.7
  Multi-Layer board cut-out: 3.65,-5.7 3.591,-5.44 3.424,-5.231 3.184,-5.115 2.917,-5.115 2.676,-5.231 2.509,-5.44 2.45,-5.7 2.45,-5.7 2.509,-5.96 2.676,-6.169 2.917,-6.285 3.184,-6.285 3.424,-6.169 3.591,-5.96 3.65,-5.7
  silkscreen extent -7.26,-9.7 8,5.3
USB-C-SMD_HC-TYPE-C-24P-FLS-CH5.06-5A-23 [mm]
  oval 1x2.05 hole 0.6 slot 1.65 at 90 deg: 0(-3,4.05) 0(-3,-4.05) 0(3,4.05) 0(3,-4.05)
  rect 1.625x0.28 smd: A1(1.138,2.751) A2(1.138,2.251) A3(1.138,1.751) A4(1.138,1.251) A5(1.138,0.751) A6(1.138,0.251) A7(1.138,-0.249) A8(1.138,-0.749) A9(1.138,-1.249) A10(1.138,-1.749) A11(1.138,-2.249) A12(1.138,-2.749) B1(-1.138,-2.751) B2(-1.138,-2.251) B3(-1.138,-1.751) B4(-1.138,-1.251) B5(-1.138,-0.751) B6(-1.138,-0.251) B7(-1.138,0.249) B8(-1.138,0.749) B9(-1.138,1.249) B10(-1.138,1.749) B11(-1.138,2.249) B12(-1.138,2.749)
  Board Outline Layer circle w0.005: c0,3.8 r0.6
  Board Outline Layer circle w0.005: c0,-3.8 r0.5
  Board Outline Layer region: 0,4.4 0.26,4.341 0.469,4.174 0.585,3.934 0.585,3.667 0.469,3.426 0.26,3.26 0,3.2 0,3.2 -0.26,3.26 -0.469,3.426 -0.585,3.667 -0.585,3.934 -0.469,4.174 -0.26,4.341 0,4.4
  Board Outline Layer region: 0,-3.3 0.217,-3.35 0.391,-3.488 0.487,-3.689 0.487,-3.911 0.391,-4.112 0.217,-4.251 0,-4.3 0,-4.3 -0.217,-4.251 -0.391,-4.112 -0.487,-3.911 -0.487,-3.689 -0.391,-3.488 -0.217,-3.35 0,-3.3
  Multi-Layer board cut-out: 0,4.4 0.26,4.341 0.469,4.174 0.585,3.934 0.585,3.667 0.469,3.426 0.26,3.26 0,3.2 0,3.2 -0.26,3.26 -0.469,3.426 -0.585,3.667 -0.585,3.934 -0.469,4.174 -0.26,4.341 0,4.4
  Multi-Layer board cut-out: 0,-3.3 0.217,-3.35 0.391,-3.488 0.487,-3.689 0.487,-3.911 0.391,-4.112 0.217,-4.251 0,-4.3 0,-4.3 -0.217,-4.251 -0.391,-4.112 -0.487,-3.911 -0.487,-3.689 -0.391,-3.488 -0.217,-3.35 0,-3.3
  silkscreen extent -2.27,-9.55 2.27,4.99
USON-10_L2.5-W1.0-P0.50-BL [mm]
  rect 0.25x0.609 smd: 1(-1,-0.415) 2(-0.5,-0.415) 4(0.5,-0.415) 5(1,-0.415) 6(1,0.415) 7(0.5,0.415) 9(-0.5,0.415) 10(-1,0.415)
  rect 0.38x0.609 smd: 3(0,-0.415) 8(0,0.415)
  silkscreen extent -1.33,-1.12 1.33,0.58

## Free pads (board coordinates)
  round 196.85 hole 125.98: 1(5570.3,5024.28) 2(5570.3,7114.98)
  round 196.85 hole 106.3: 1(6998.5,5761) 1(6998.5,7060.22) 1(8888.26,5761) 1(8888.26,7060.22)
  round 160 hole 120: 1(7605.42,5159.63)
  round 24.6 smd far side: 2(7339.93,5160.05)
  round 24.6 smd: 2(7340.93,5157.58)
  rect 28x165 smd: 10(7670.45,4797.08) 10(7709.45,4797.08) 10(7748.45,4797.08) 10(7787.45,4797.08) 10(7826.45,4797.08) 10(7865.45,4797.08) 18(7904.45,4797.08) B1(7155.45,4797.08) B2(7194.45,4797.08) B3(7233.45,4797.08) B4(7272.45,4797.08) B5(7311.45,4797.08) B6(7350.45,4797.08) B7(7389.45,4797.08) B8(7428.45,4797.08) B9(7467.45,4797.08) B10(7506.45,4797.08) B11(7545.45,4797.08)
  rect 28x165 smd far side: 10(7670.45,4797.08) 10(7709.45,4797.08) 10(7748.45,4797.08) 10(7787.45,4797.08) 10(7826.45,4797.08) 10(7865.45,4797.08) 18(7904.45,4797.08) A1(7155.45,4797.08) A2(7194.45,4797.08) A3(7233.45,4797.08) A4(7272.45,4797.08) A5(7311.45,4797.08) A6(7350.45,4797.08) A7(7389.45,4797.08) A8(7428.45,4797.08) A9(7467.45,4797.08) A10(7506.45,4797.08) A11(7545.45,4797.08)

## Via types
v1: diameter 15.7, hole 11.8, Top Layer to Bottom Layer, 94 vias
v2: diameter 24, hole 12, Top Layer to Bottom Layer, 92 vias
v3: diameter 24, hole 16, Top Layer to Bottom Layer, 67 vias
v4: diameter 15.75, hole 11.81, Top Layer to Bottom Layer, 49 vias
v5: diameter 15.75, hole 11.8, Top Layer to Bottom Layer, 1 vias

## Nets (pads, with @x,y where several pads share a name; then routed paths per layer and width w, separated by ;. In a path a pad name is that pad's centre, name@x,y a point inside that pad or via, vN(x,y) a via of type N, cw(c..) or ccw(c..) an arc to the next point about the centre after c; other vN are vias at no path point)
1V2: C12.2 C13.2 C14.2 C15.2 C29.2 C30.2 L1.1 R26.2 U4.19 U4.27 U4.33 U4.41 | length 1309.6
  Top Layer w7.9: v4(6258.11,6667.18) 6265.16,6674.23 U4.19@6265.16,6705.88
  Top Layer w11: v4(6103.2,6520.16) 6137.17,6520.16 v4(6177.2,6520.13) ; v4(6103.2,6638.24) 6137.2,6638.24 v4(6177.2,6638.24) ; C14.2@6225,6350.64 6245.47,6371.12 U4.41@6245.47,6430.29 ; U4.41@6245.47,6431.55 v5(6245.47,6471.58) ; U4.19@6265.16,6705.88 6265.16,6765.68 C15.2@6285,6785.52 ; C29.2@6275.34,7120.98 6275.34,7027.08 6299.33,7003.08 6520,7003.08 6545,7028.08 L1.1@6545,7054.62
  Bottom Layer w7.9: C12.2@6032.56,6649.18 6040.34,6656.96 6084.48,6656.96 v4(6103.2,6638.24) ; v1(6192.56,6948.08) 6226.34,6948.08 6264.42,6910 6264.42,6673.49 v4(6258.11,6667.18)
  Bottom Layer w10: C13.2@6032.56,6500.27 6083.31,6500.27 v4(6103.2,6520.16)
3V3: C8.2 C19.2 C20.2 C21.2 C28.2 C31.2 C35.2 JP1.92 JP1.93 R13.2 R14.2 R17.2 R23.2 R24.2 R25.2 R33.2 R34.2 R35.2 RELAY_0.3 U2.4 U2.5 U3.2 U4.16 U4.23 U4.44 U5.8 U6.3 U6.4 U7.2 | length 2481.2
  Top Layer w7.9: v3(5945.74,7087.93) R35.2@5945.74,7152.93 ; v4(6324.22,6667.67) U4.16@6324.21,6705.88 ; v3(6659.94,7199.13) R34.2@6711.08,7199.13 ; RELAY_0.3@8321.59,5265 v3(8399.73,5265)
  Top Layer w11: R17.2@5970,6291.79 6030,6291.79 6061.3,6323.09 6267.44,6323.09 C19.2@6295,6350.64 6304.53,6360.17 U4.44@6304.53,6430.29 v1(6304.53,6471.58) ; U4.23@6186.42,6705.88 6186.42,6756.94 C21.2@6215,6785.52 6242.56,6813.08 6327.44,6813.08 C20.2@6355,6785.52 ; U4.16@6324.21,6705.88 6324.21,6728.08 6355,6758.87 C20.2@6355,6785.52 ; v1(6448.31,6680.52) 6571.83,6680.52 U5.8@6574.39,6683.08 v1(6643.7,6683.08) ; R24.2@6500,6872.74 R25.2@6435,6872.74 6412.14,6872.74 6395,6855.61 6395,6825.52 C20.2@6355,6785.52
  Top Layer w11.8: U6.4@6401.46,7142.77 U6.3@6458.54,7142.77 6458.54,7197.1 C31.2@6457.56,7198.08
  Top Layer w20: U7.2@6711.97,6580 6741.97,6550 v2(6825.99,6550) 6825.99,6507.77 6805.99,6487.77 U3.2@6742.87,6487.77
  Top Layer w23.7: v1(8253.4,5751.6) v1(8313.4,5751.6) v1(8373.4,5751.6) ; v1@8313.4,5756.6 8313.4,5807.25
  Bottom Layer w7.9: R33.2@8204.76,5880 8204.76,5800.24 v1(8253.4,5751.6)
  Bottom Layer w11: R14.2@5631.3,5833.09 R13.2@5631.3,5913.09
  Bottom Layer w19.3: U2.5@7377.22,6081.35 7501.76,6081.35 C8.2@7519.62,6099.21 7610.21,6099.21 v3(7624.42,6085)
  other v1: 8283.4,5751.6 8343.4,5751.6 8313.4,5776.93
  other v2: 5631.3,5873.09
  other v3: 6513.74,7179.83 6546.64,7179.83 6513.74,7213.83 6546.64,7213.83
  other v4: 6186.42,6743.08
5V: C1.1 C5.2 C9.1 C10.1 D3.1 HDR2.1 HDR2.3 JP1.7 JP1.8 JP1.9 JP1.10 JP1.11 JP1.12 U1.4 U1.5 USB1.A4 USB1.A9 USB1.B4 USB1.B9 | length 610.8
  Top Layer w10: JP1.12@8260.12,5686.62 JP1.7@8334.92,5686.62 ; JP1.12@8260.22,5668.87 JP1.7@8334.92,5668.87 ; JP1.12@8260.22,5677.79 JP1.7@8334.92,5677.79
  Top Layer w11: v3(5710.17,5440) 5714.04,5440 5730.17,5423.87 USB1.B4@5730.17,5389.8 ; v3(5710.87,5250) 5714.12,5250 5730.25,5266.12 USB1.A9@5730.25,5300.2 ; USB1.B9@5828.59,5389.8 5828.59,5423.87 5844.72,5440 v3(5847.97,5440) ; USB1.A4@5828.67,5300.2 5828.67,5266.13 5844.8,5250 v3(5848.67,5250)
  Top Layer w20: C5.2@8475,5400.52 8492.86,5382.66 U1.4@8537.6,5382.66 U1.5@8612.4,5382.66
  other v2: 6004.42,5305 6039.42,5305 6004.42,5345 6039.42,5345 6004.42,5385 6039.42,5385
12V: pad.A2 pad.A3 pad.B1 pad.B2 pad.B3 R29.2 | length 1861.5
  Top Layer w20: pad.B1@7155.45,4797.08 7155.45,4976.03 v2(7169.42,4990) 7194.45,4964.97 ; pad.B2@7194.45,4797.08 7194.45,4964.97 ; pad.B3@7233.45,4797.08 7233.45,4925.97 7194.45,4964.97 ; v3(7675.65,5350) R29.2@7729.76,5350
  Bottom Layer w20: pad.A2@7194.45,4797.08 7194.45,4964.97 ; pad.A3@7233.45,4797.08 7233.45,4925.97 7194.45,4964.97 ; v3(7675.65,5350) 7224.42,5350 7169.42,5295 v2(7169.42,4990) 7194.45,4964.97
$1N34953: R3.2 RELAY_1.2 | length 116.3
  Top Layer w20: R3.2@9219.08,5695 9239.42,5715.34 RELAY_1.2@9239.42,5802.83
$1N34959: R4.2 RELAY_2.2 | length 116.3
  Top Layer w7.9: RELAY_2.2@9139.42,7037.17 9139.42,7124.66 R4.2@9159.76,7145
$1N39035: R29.1 RELAY_0.1 | length 184.4
  Top Layer w20: R29.1@7789.08,5350 7858.14,5350 v3(7873.14,5365) RELAY_0.1@7967.25,5365
$2N4077: JP1.89 R33.1 | length 78.8
  Top Layer w7.9: JP1.89@8258.14,5803.95 8258.14,5833.72 v1(8264.42,5840)
  Bottom Layer w7.9: R33.1@8264.08,5880 8264.08,5840.34 v1(8264.42,5840)
$2N22853: BOOT.1 C32.1 R30.2 | length 230.6
  Bottom Layer w7.9: C32.1@8691.98,6055 8723.4,6055 BOOT.1@8758.4,6020 8723.4,5985 R30.2@8694.08,5985 8694.08,6052.9 C32.1@8691.98,6055
$2N22954: C33.1 R31.2 RECOVERY.1 | length 230.6
  Bottom Layer w7.9: C33.1@8691.98,6335 8694.08,6332.9 R31.2@8694.08,6265 8723.4,6265 RECOVERY.1@8758.4,6300 8723.4,6335 C33.1@8691.98,6335
$2N22981: C34.1 R32.2 RESET.1 | length 230.6
  Bottom Layer w7.9: C34.1@8691.98,6195 8694.08,6192.9 R32.2@8694.08,6125 8723.4,6125 RESET.1@8758.4,6160 8723.4,6195 C34.1@8691.98,6195
$2N23475: Q1.3 WORKING.1 | length 71.4
  Top Layer w7.9: WORKING.1@6709.26,7133.99 6709.26,7107.14 Q1.3@6740.74,7075.67
$2N23477: R34.1 WORKING.2 | length 65.6
  Top Layer w7.9: R34.1@6770.4,7199.13 6772.21,7197.31 WORKING.2@6772.21,7134.27
$2N23478: PWR.2 R35.1 | length 65.9
  Top Layer w7.9: PWR.2@5880.6,7214.06 5943.92,7214.06 R35.1@5945.74,7212.25
$4N2459: R9.2 U1.3 | length 73.8
  Top Layer w19.3: R9.2@8515.34,5538.08 8537.6,5515.82 U1.3@8537.6,5473.5
$4N5121: D1.3 USBOTG/1.6 | length 138.1
  Top Layer w6.2: D1.3@8965.24,5485.48 8972.28,5485.48 8995.44,5462.33 8995.44,5455.28 8995.54,5455.18 9030,5455.18 9036.42,5461.6 9036.42,5485.38 9049.12,5498.08 USBOTG/1.6@9055,5498.08
$4N5134: D1.1 USBOTG/1.4 | length 138.1
  Top Layer w6.2: D1.1@8965.24,5410.68 8972.28,5410.68 8995.44,5433.84 8995.44,5440.89 8995.54,5440.98 9030,5440.98 9036.42,5434.57 9036.42,5410.79 9049.12,5398.08 USBOTG/1.4@9055,5398.08
$4N5413: D2.3 USBOTG/1.3 | length 747
  Top Layer w6.2: D2.3@8900.24,5310.48 8907.28,5310.48 8930.44,5287.33 8930.44,5280.28 8930.54,5280.18 8960.3,5280.18 9011.29,5229.2 9223.54,5229.2 9259.38,5265.04 9259.38,5290.58 ccw(c9252.16,5290.58) 9252.16,5297.8 cw(c9252.16,5305.03) 9244.93,5305.03 9244.93,5305.58 cw(c9252.16,5305.58) 9252.16,5312.8 ccw(c9252.16,5320.03) 9259.38,5320.03 9259.38,5320.58 ccw(c9252.16,5320.58) 9252.16,5327.8 cw(c9252.16,5335.03) 9244.93,5335.03 9244.93,5335.58 cw(c9252.16,5335.58) 9252.16,5342.8 ccw(c9252.16,5350.03) 9259.38,5350.03 9259.38,5350.58 ccw(c9252.16,5350.58) 9252.16,5357.8 cw(c9252.16,5365.03) 9244.93,5365.03 9244.93,5365.58 cw(c9252.16,5365.58) 9252.16,5372.8 ccw(c9252.16,5380.03) 9259.38,5380.03 9259.38,5420 9238.39,5440.98 9197.9,5440.98 USBOTG/1.3@9155,5398.08
$4N5415: D2.1 USBOTG/1.5 | length 744.6
  Top Layer w6.2: D2.1@8900.24,5235.68 8907.28,5235.68 8930.44,5258.84 8930.44,5265.89 8930.54,5265.98 8954.42,5265.98 9005.4,5215 9229.42,5215 9273.58,5259.16 9273.58,5425.88 9244.28,5455.18 9197.9,5455.18 USBOTG/1.5@9155,5498.08
$4N7460: R12.2 U2.3 | length 67.9
  Bottom Layer w19.3: U2.3@7452.02,6172.19 7452.02,6228.83 R12.2@7459.96,6236.77
$4N7470: CARD1.CD R11.2 | length 124.8
  Bottom Layer w5.4: R11.2@7228.32,6281.77 7236.75,6290.2 CARD1.CD@7236.75,6403.11
$4N7739: C11.2 ETH1.P1 | length 122.7
  Bottom Layer w10: ETH1.P1@6181.45,6098.28 6223.17,6140 C11.2@6286.86,6140
$4N7747: ETH1.14 R14.1 | length 249.1
  Bottom Layer w10: R14.1@5570.34,5833.08 5570.34,5680.46 ETH1.14@5638.54,5612.26
$4N7748: ETH1.11 R13.1 | length 249.1
  Bottom Layer w10: R13.1@5570.34,5913.08 5570.34,6065.71 ETH1.11@5638.54,6133.91
$4N11549: R16.2 USB1.A5 | length 85.2
  Top Layer w11: USB1.A5@5808.99,5300.2 5809.08,5300.11 R16.2@5809.08,5215
$4N11575: R15.1 USB1.B5 | length 85.2
  Top Layer w11: R15.1@5749.76,5475 5749.85,5474.91 USB1.B5@5749.85,5389.8
$6N3350: R18.2 U4.3 | length 161.3
  Top Layer w4.9: U4.3@6412.8,6499.19 6497.64,6499.19 6518.74,6478.09 R18.2@6565.34,6478.09
$6N3355: C25.2 C26.2 U4.6 U4.7 U4.8 U7.1 | length 288.4
  Top Layer w11: U4.6@6412.8,6558.24 6442.8,6558.24 6467.95,6533.08 C26.2@6502.44,6533.08 ; U4.7@6412.8,6577.93 v1@6453.36,6577.93 ; U4.8@6412.8,6597.61 6442.8,6597.61 6468.27,6623.08 C25.2@6502.44,6623.08
  Top Layer w20: v2(6609.22,6579.97) U7.1@6656.84,6579.97
  other v1: 6452.8,6553.24 6452.8,6577.93 6452.8,6602.61
$6N3428: R22.1 U4.40 | length 118.1
  Top Layer w5: R22.1@6160,6353.08 6160,6358.08 6183.29,6381.37 6206.53,6381.37 6225.79,6400.63 U4.40@6225.79,6430.29
$6N3531: LED1.2 R17.1 | length 293.2
  Top Layer w4.9: R17.1@5970,6352.74 5944.66,6352.74 5935,6343.08 5935,6267.15 5944.66,6257.49 6061.02,6257.49 LED1.2@6095.14,6291.61
$6N6824: C27.2 HDMI1.18 R19.2 R20.1 R21.1 | length 130.7
  Top Layer w7.9: HDMI1.18@5852.28,6805.57 5972.82,6805.57 R21.1@5980,6812.74
$6N28730: L1.2 U6.2 | length 87.1
  Top Layer w11.8: U6.2@6458.54,7123.08 6543.47,7123.08 L1.2@6545,7121.55
$6N28750: C29.1 R26.1 R27.2 U6.5 | length 205.2
  Top Layer w11.8: R26.1@6336.3,7053.08 R27.2@6336.3,7193.08 ; C29.1@6336.3,7123.08 U6.5@6401.46,7123.08
A3V3: C16.2 C17.2 C18.2 C23.2 U3.1 U4.24 U4.30 U4.47 | length 1444
  Top Layer w11: v4(6103.2,6579.18) 6137.2,6579.18 v4(6177.2,6579.18) ; C16.2@6145,6785.52 6166.73,6763.79 U4.24@6166.73,6686.71 ; U4.24@6166.73,6707.14 U4.24@6166.73,6686.71 ; v4(6176.73,6667.18) 6176.73,6676.71 U4.24@6166.73,6686.71 ; U4.47@6363.58,6430.29 6363.58,6352.06 C18.2@6365,6350.64 ; U4.47@6363.58,6431.55 v1(6363.58,6471.58) ; v1(6631.31,6422.77) C23.2@6687.76,6422.77 U3.1@6687.76,6487.77
  3V3 w11: v4(6176.73,6667.18) 6137.2,6627.66 6137.2,6579.18 ; v4(6177.2,6579.18) 6137.2,6579.18 ; v1(6631.31,6422.77) 6412.4,6422.77 v1(6363.58,6471.58) 6323.55,6431.55 6166.73,6431.55 6137.2,6461.07 6137.2,6579.18
  Bottom Layer w7.9: C17.2@6032.56,6579.18 6050.37,6596.99 6085.39,6596.99 v4(6103.2,6579.18) 6085.39,6561.38 6050.37,6561.38 C17.2@6032.56,6579.18
BOOT-SW: JP1.4 R30.1 | length 621.9
  Top Layer w7.9: JP1.4@8384.13,5677.97 8384.13,5635.29 8404.42,5615 8529.42,5615 8569.42,5655 8569.42,5885 8614.42,5930 v3(8634.76,5930)
  Bottom Layer w7.9: v3(8634.76,5930) R30.1@8634.76,5985
CM_SCL: JP1.90
CM_SDA: JP1.91
DM_OTG: D1.6 JP2.49 | length 2538.6
  Top Layer w6.2: JP2.49@7675.56,7016.4 7675.56,6996.42 7676.34,6995.64 7676.34,6955.87 7714.12,6918.08 8436.25,6918.08 8705.22,6649.12 8705.22,5664.28 8816.42,5553.08 8816.42,5453.69 8829.12,5440.98 8844.46,5440.98 8844.56,5440.89 8844.56,5433.84 8867.72,5410.68 D1.6@8874.76,5410.68
DP_OTG: D1.4 JP2.48 | length 2537.7
  Top Layer w6.2: JP2.48@7691.31,7016.4 7691.31,6996.42 7690.54,6995.64 7690.54,6961.75 7720,6932.28 7746.43,6932.28 7750.81,6936.67 7750.81,6938.7 7755.2,6943.08 7806.43,6943.08 7810.81,6938.7 7810.81,6936.67 7815.2,6932.28 7866.43,6932.28 7870.81,6936.67 7870.81,6938.7 7875.2,6943.08 7926.43,6943.08 7930.81,6938.7 7930.81,6936.67 7935.2,6932.28 8442.14,6932.28 8719.42,6655 8719.42,5670.16 8830.62,5558.97 8830.62,5459.57 8835,5455.18 8844.46,5455.18 8844.56,5455.28 8844.56,5462.33 8867.72,5485.48 D1.4@8874.76,5485.48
